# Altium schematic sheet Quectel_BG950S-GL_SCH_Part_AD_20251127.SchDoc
size A1
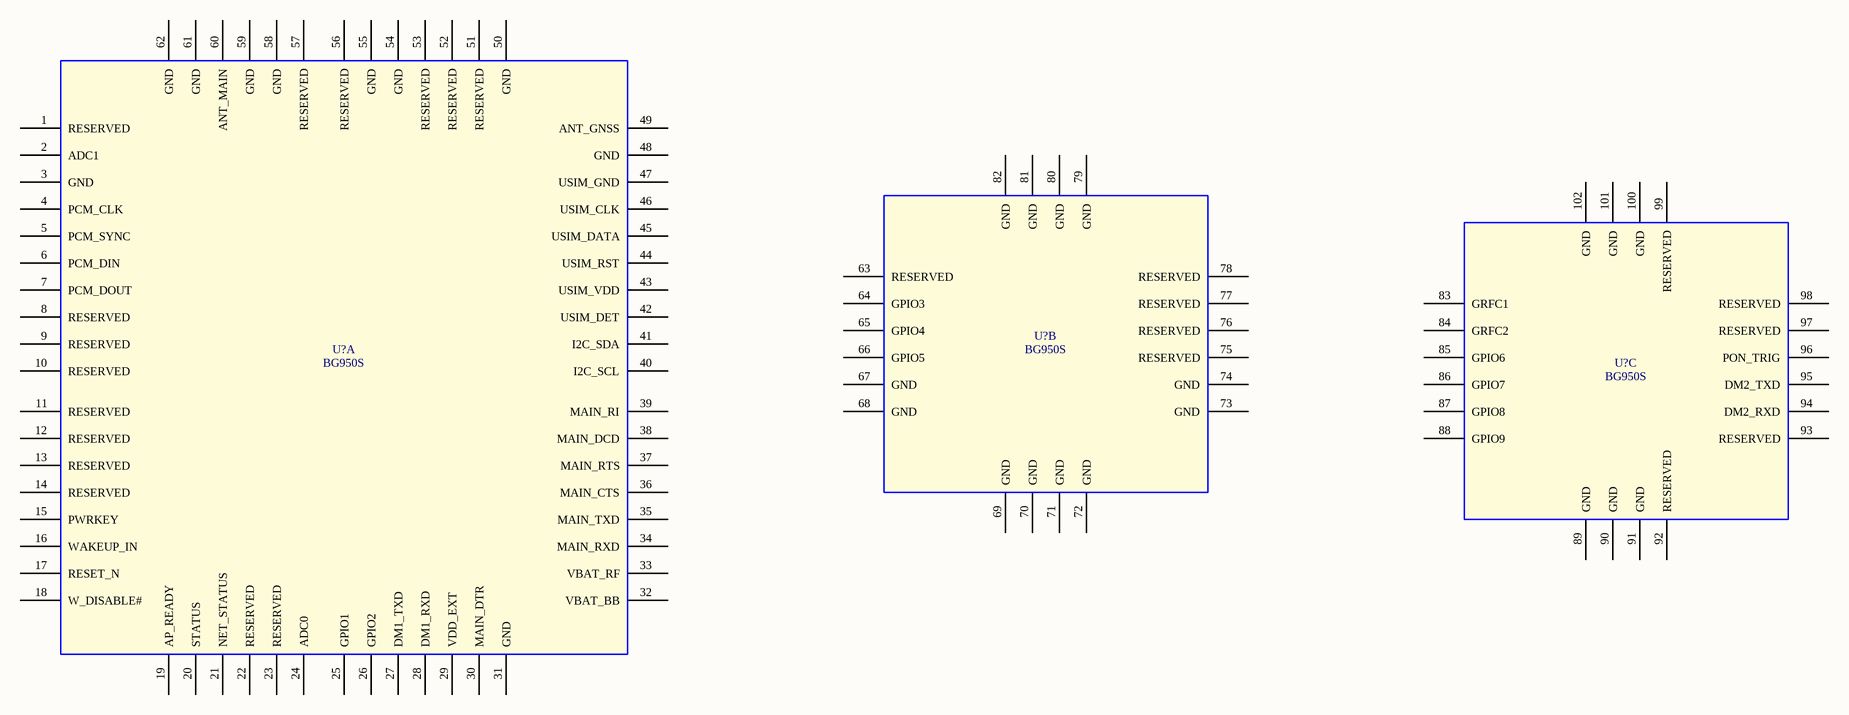
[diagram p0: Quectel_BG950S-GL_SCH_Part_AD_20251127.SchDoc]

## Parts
(Parts that share a designator on the sheet are numbered #1, #2 ... from top to bottom, then left to right.)
U?#1  BG950S  [BG950S]  (part B of 3)
U?#2  BG950S  [BG950S]  (part A of 3)
U?#3  BG950S  [BG950S]  (part C of 3)

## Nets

Not connected (* = marked no-connect by the designer): U?#1 63(RESERVED) 64(GPIO3) 65(GPIO4) 66(GPIO5) 67(GND) 68(GND) 69(GND) 70(GND) 71(GND) 72(GND) 73(GND) 74(GND) 75(RESERVED) 76(RESERVED) 77(RESERVED) 78(RESERVED) 79(GND) 80(GND) 81(GND) 82(GND); U?#2 1(RESERVED) 2(ADC1) 3(GND) 4(PCM_CLK) 5(PCM_SYNC) 6(PCM_DIN) 7(PCM_DOUT) 8(RESERVED) 9(RESERVED) 10(RESERVED) 11(RESERVED) 12(RESERVED) 13(RESERVED) 14(RESERVED) 15(PWRKEY) 16(WAKEUP_IN) 17(RESET_N) 18(W_DISABLE#) 19(AP_READY) 20(STATUS) 21(NET_STATUS) 22(RESERVED) 23(RESERVED) 24(ADC0) 25(GPIO1) 26(GPIO2) 27(DM1_TXD) 28(DM1_RXD) 29(VDD_EXT) 30(MAIN_DTR) 31(GND) 32(VBAT_BB) 33(VBAT_RF) 34(MAIN_RXD) 35(MAIN_TXD) 36(MAIN_CTS) 37(MAIN_RTS) 38(MAIN_DCD) 39(MAIN_RI) 40(I2C_SCL) 41(I2C_SDA) 42(USIM_DET) 43(USIM_VDD) 44(USIM_RST) 45(USIM_DATA) 46(USIM_CLK) 47(USIM_GND) 48(GND) 49(ANT_GNSS) 50(GND) 51(RESERVED) 52(RESERVED) 53(RESERVED) 54(GND) 55(GND) 56(RESERVED) 57(RESERVED) 58(GND) 59(GND) 60(ANT_MAIN) 61(GND) 62(GND); U?#3 83(GRFC1) 84(GRFC2) 85(GPIO6) 86(GPIO7) 87(GPIO8) 88(GPIO9) 89(GND) 90(GND) 91(GND) 92(RESERVED) 93(RESERVED) 94(DM2_RXD) 95(DM2_TXD) 96(PON_TRIG) 97(RESERVED) 98(RESERVED) 99(RESERVED) 100(GND) 101(GND) 102(GND)

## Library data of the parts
U?#1-U?#3 = BG950S: BG950S-GL Module 102PIN 19.9x23.6mm H2.4mm RO; Manufacturer: QUECTEL; Geometry.Height: 2.4mm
